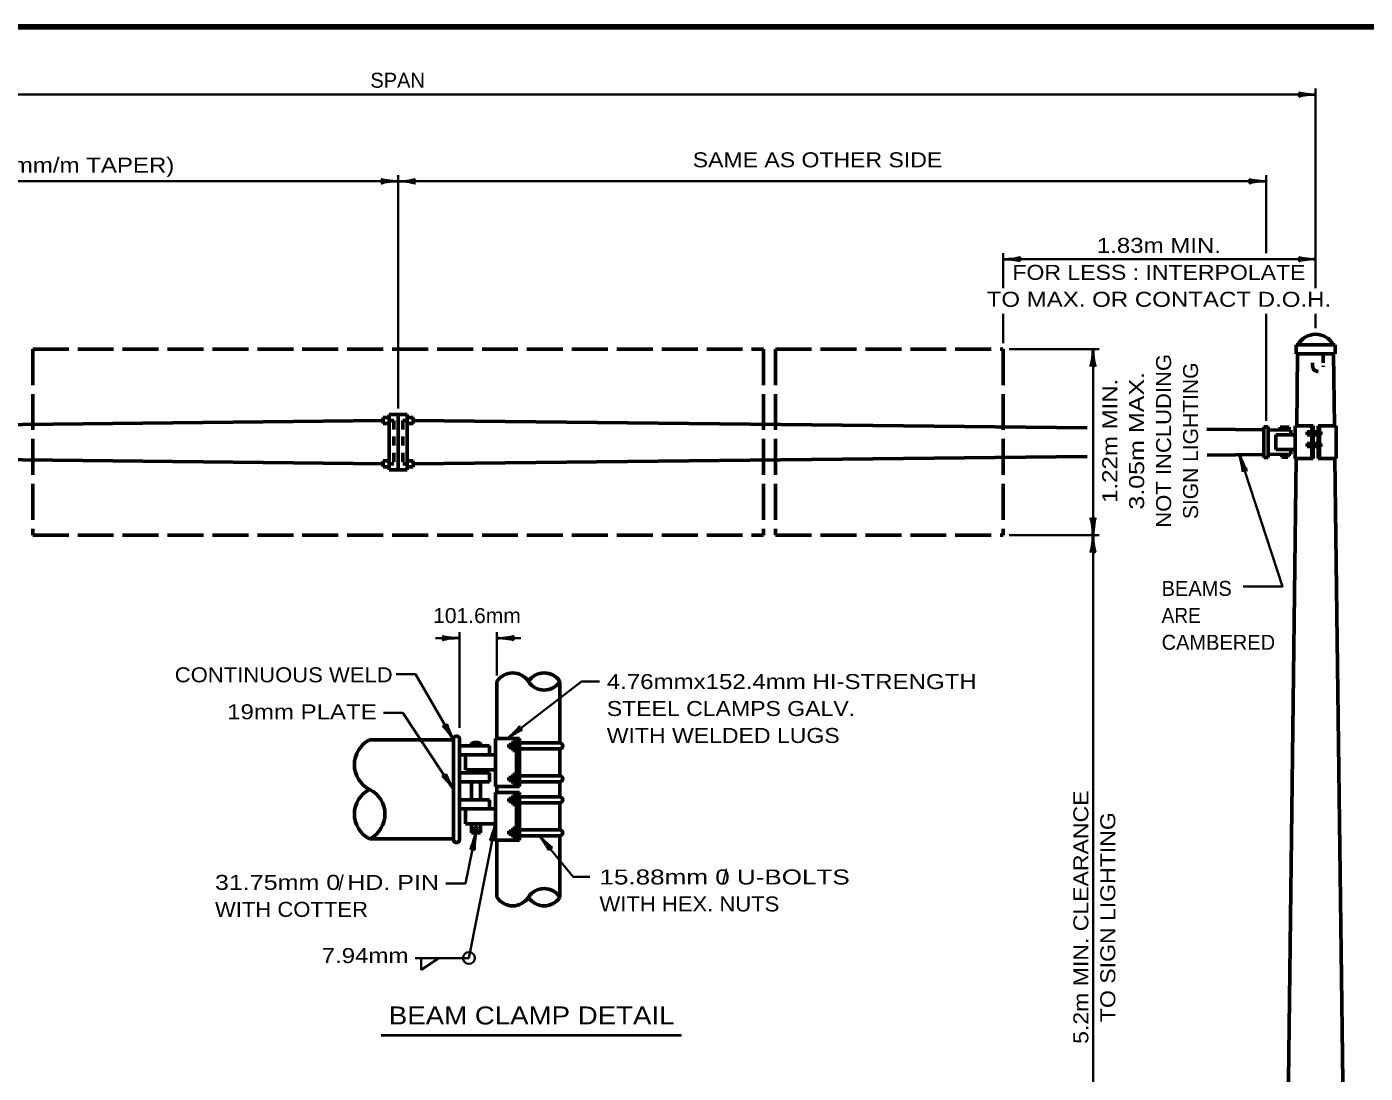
# Model space of a CAD drawing. Extents: x -46 to 809, y -15 to 529.
# Drawn here: x 209.6 to 477.7, y 313 to 522.6 of the extents above; entities that cross this region are included whole.
import ezdxf
from ezdxf.enums import TextEntityAlignment as Align

# ---------------------------------------------------------------- set-up
doc = ezdxf.new("R2010")
doc.units = 0
doc.header["$LTSCALE"] = 1.2
doc.linetypes.add('LONG_DASHED', pattern=[7.5, 6, -1.5])
doc.linetypes.add('SHORT_DASHED', pattern=[2.7, 1.5, -1.2])
doc.layers.add('1', color=7, linetype='Continuous', lineweight=35)

msp = doc.modelspace()

# ---------------------------------------------------------------- linework, layer by layer
at = {"layer": '1'}
for p, q in [((467.782, 470.197), (467.782, 510.163)), ((100.214, 508.963), (467.782, 508.963)), ((109.698, 491.614), (283.998, 491.614)), ((283.998, 446.114), (283.998, 492.814)), ((283.998, 491.614), (457.848, 491.614)), ((457.848, 477.203), (457.848, 492.814)), ((405.198, 470.197), (405.198, 477.203)), ((405.198, 476.003), (467.782, 476.003)), ((405.198, 459.203), (405.198, 465.037)), ((457.848, 443.614), (457.848, 465.037)), ((467.782, 462.163), (467.782, 465.037)), ((406.398, 458.003), (424.398, 458.003)), ((406.398, 420.725), (424.398, 420.725)), ((291.486, 400.126), (296.286, 400.126)), ((296.286, 382.126), (296.286, 401.326)), ((303.786, 392.626), (303.786, 401.326)), ((303.786, 400.126), (308.586, 400.126)), ((303.486, 362.925), (298.175, 336.055)), ((298.175, 336.055), (287.375, 336.055)), ((288.575, 336.055), (288.575, 333.655)), ((292.175, 336.055), (288.575, 333.655))]:
    msp.add_line(p, q, dxfattribs=at)
at = {"layer": '1', "lineweight": 53}
for p, q in [((471.682, 458.863), (463.882, 458.863)), ((463.882, 458.863), (463.882, 457.063)), ((471.682, 458.863), (471.682, 457.063)), ((471.682, 457.063), (463.882, 457.063)), ((464.182, 457.063), (463.998, 442.664)), ((471.382, 457.063), (471.566, 442.664)), ((110.598, 441.824), (280.998, 443.714)), ((280.998, 444.314), (280.998, 443.114)), ((280.998, 444.314), (282.198, 444.314)), ((280.998, 443.114), (282.198, 443.114)), ((282.198, 444.914), (282.198, 433.814)), ((282.198, 444.914), (283.998, 444.914)), ((283.998, 444.914), (283.998, 433.814)), ((285.798, 444.914), (283.998, 444.914)), ((285.798, 444.914), (285.798, 433.814)), ((286.998, 444.314), (285.798, 444.314)), ((286.998, 443.114), (285.798, 443.114)), ((286.998, 444.314), (286.998, 443.114)), ((421.998, 442.217), (286.998, 443.714)), ((457.398, 442.414), (457.398, 436.314)), ((458.298, 442.414), (457.398, 442.414)), ((458.298, 442.414), (458.298, 436.314)), ((463.698, 442.664), (467.298, 442.664)), ((463.698, 442.664), (463.698, 436.064)), ((466.998, 442.664), (466.998, 436.064)), ((467.298, 442.664), (467.298, 436.064)), ((471.866, 442.664), (468.266, 442.664)), ((468.266, 442.664), (468.266, 436.064)), ((468.566, 442.664), (468.566, 436.064)), ((471.866, 442.664), (471.866, 436.064)), ((457.398, 441.824), (446.011, 441.95)), ((462.798, 441.764), (458.298, 441.814)), ((459.798, 440.864), (459.798, 437.864)), ((459.798, 440.864), (463.698, 440.864)), ((460.698, 441.768), (460.698, 442.368)), ((462.498, 442.368), (460.698, 442.368)), ((462.498, 441.768), (462.498, 442.368)), ((462.798, 441.764), (462.798, 440.864)), ((466.698, 441.464), (466.098, 441.464)), ((466.098, 441.464), (466.098, 440.864)), ((466.698, 440.864), (466.098, 440.864)), ((466.998, 441.764), (466.698, 441.764)), ((466.698, 441.764), (466.698, 440.564)), ((466.998, 440.564), (466.698, 440.564)), ((468.266, 441.464), (467.298, 441.464)), ((468.266, 440.864), (467.298, 440.864)), ((459.798, 437.864), (463.698, 437.864)), ((462.798, 437.864), (462.798, 436.964)), ((466.698, 439.064), (466.098, 439.064)), ((466.098, 439.064), (466.098, 438.464)), ((466.698, 438.464), (466.098, 438.464)), ((466.998, 439.364), (466.698, 439.364)), ((466.698, 439.364), (466.698, 438.164)), ((466.998, 438.164), (466.698, 438.164)), ((468.266, 439.064), (467.298, 439.064)), ((468.266, 438.464), (467.298, 438.464)), ((110.598, 436.904), (280.998, 435.014)), ((280.998, 435.614), (280.998, 434.414)), ((280.998, 435.614), (282.198, 435.614)), ((280.998, 434.414), (282.198, 434.414)), ((286.998, 435.614), (285.798, 435.614)), ((286.998, 434.414), (285.798, 434.414)), ((421.998, 436.512), (286.998, 435.014)), ((286.998, 435.614), (286.998, 434.414)), ((457.398, 436.904), (446.068, 436.779)), ((458.298, 436.314), (457.398, 436.314)), ((462.798, 436.964), (458.298, 436.914)), ((460.998, 436.344), (460.998, 436.944)), ((462.198, 436.358), (460.998, 436.344)), ((463.914, 436.064), (461.782, 269.263)), ((462.198, 436.358), (462.198, 436.958)), ((463.698, 436.064), (467.298, 436.064)), ((471.866, 436.064), (468.266, 436.064)), ((471.651, 436.064), (473.782, 269.263)), ((282.198, 433.814), (283.998, 433.814)), ((285.798, 433.814), (283.998, 433.814)), ((303.786, 391.425), (303.786, 380.026)), ((316.386, 391.425), (316.386, 379.126)), ((295.086, 379.726), (278.286, 379.726)), ((295.086, 379.726), (295.086, 359.925)), ((296.286, 379.726), (296.286, 359.925)), ((296.286, 378.526), (302.286, 378.526)), ((302.286, 376.726), (302.286, 378.526)), ((308.286, 380.026), (303.486, 380.026)), ((303.486, 380.026), (303.486, 370.425)), ((306.936, 378.826), (306.186, 378.826)), ((306.186, 378.826), (306.186, 378.226)), ((306.936, 378.226), (306.186, 378.226)), ((307.686, 379.425), (306.936, 379.425)), ((306.936, 379.425), (306.936, 377.626)), ((307.686, 380.026), (307.686, 370.425)), ((308.286, 380.026), (308.286, 370.425)), ((308.286, 379.126), (316.386, 379.126)), ((296.286, 376.726), (303.486, 376.726)), ((297.486, 376.726), (297.486, 373.726)), ((307.686, 377.626), (306.936, 377.626)), ((308.286, 377.925), (316.386, 377.925)), ((316.386, 377.925), (316.386, 372.526)), ((296.286, 373.126), (302.286, 373.126)), ((297.486, 373.726), (303.486, 373.726)), ((298.686, 373.726), (298.686, 373.126)), ((300.486, 373.726), (300.486, 373.126)), ((302.286, 373.126), (302.286, 371.326)), ((307.686, 372.826), (306.936, 372.826)), ((306.936, 372.826), (306.936, 371.026)), ((296.286, 371.326), (302.286, 371.326)), ((298.686, 371.326), (298.686, 367.726)), ((300.486, 371.326), (300.486, 367.726)), ((308.286, 370.425), (303.486, 370.425)), ((303.786, 370.425), (303.786, 369.226)), ((306.936, 372.226), (306.186, 372.226)), ((306.186, 372.226), (306.186, 371.626)), ((306.936, 371.626), (306.186, 371.626)), ((307.686, 371.026), (306.936, 371.026)), ((308.286, 372.526), (316.386, 372.526)), ((308.286, 371.326), (316.386, 371.326)), ((316.386, 371.326), (316.386, 368.326)), ((296.286, 367.726), (302.286, 367.726)), ((302.286, 365.925), (302.286, 367.726)), ((308.286, 369.226), (303.486, 369.226)), ((303.486, 369.226), (303.486, 359.626)), ((306.936, 368.026), (306.186, 368.026)), ((306.186, 368.026), (306.186, 367.425)), ((306.936, 367.425), (306.186, 367.425)), ((307.686, 368.626), (306.936, 368.626)), ((306.936, 368.626), (306.936, 366.826)), ((307.686, 369.226), (307.686, 359.626)), ((308.286, 369.226), (308.286, 359.626)), ((308.286, 368.326), (316.386, 368.326)), ((296.286, 365.925), (303.486, 365.925)), ((297.486, 365.925), (297.486, 362.925)), ((307.686, 366.826), (306.936, 366.826)), ((308.286, 367.126), (316.386, 367.126)), ((316.386, 367.126), (316.386, 361.726)), ((297.486, 362.925), (303.486, 362.925)), ((298.686, 362.925), (298.686, 361.126)), ((300.486, 362.925), (300.486, 361.126)), ((307.686, 362.026), (306.936, 362.026)), ((306.936, 362.026), (306.936, 360.226)), ((295.086, 359.925), (278.286, 359.925)), ((298.686, 361.126), (300.486, 361.126)), ((308.286, 359.626), (303.486, 359.626)), ((303.786, 359.626), (303.786, 348.226)), ((306.936, 361.425), (306.186, 361.425)), ((306.186, 361.425), (306.186, 360.826)), ((306.936, 360.826), (306.186, 360.826)), ((307.686, 360.226), (306.936, 360.226)), ((308.286, 361.726), (316.386, 361.726)), ((308.286, 360.526), (316.386, 360.526)), ((316.386, 360.526), (316.386, 348.226))]:
    msp.add_line(p, q, dxfattribs=at)
at = {"layer": '1', "linetype": 'LONG_DASHED', "lineweight": 53}
for p, q in [((210.798, 458.003), (210.798, 420.725)), ((210.798, 458.003), (357.198, 458.003)), ((357.198, 458.003), (357.198, 420.725)), ((359.598, 458.003), (359.598, 420.725)), ((359.598, 458.003), (405.198, 458.003)), ((405.198, 458.003), (405.198, 420.725)), ((210.798, 420.725), (357.198, 420.725)), ((359.598, 420.725), (405.198, 420.725))]:
    msp.add_line(p, q, dxfattribs=at)
at = {"layer": '1', "linetype": 'SHORT_DASHED', "lineweight": 53}
for p, q in [((469.282, 457.063), (469.282, 454.663)), ((467.182, 455.263), (467.182, 454.663)), ((282.198, 443.714), (283.098, 443.714)), ((283.098, 443.714), (283.098, 435.014)), ((284.898, 443.714), (284.898, 435.014)), ((285.798, 443.714), (284.898, 443.714)), ((282.198, 435.014), (283.098, 435.014)), ((285.798, 435.014), (284.898, 435.014))]:
    msp.add_line(p, q, dxfattribs=at)
at = {"layer": '1', "lineweight": 40}
msp.add_line((280.598, 320.626), (340.722, 320.626), dxfattribs=at)
at = {"layer": '1', "lineweight": 158}
msp.add_lwpolyline([(802.618, 522.556), (10.918, 522.456), (11.018, -3.544)], dxfattribs=at)
at = {"layer": '1'}
for points in [[(423.198, 254.722), (423.198, 420.725), (423.198, 458.003)], [(452.547, 436.851), (461.153, 410.487), (453.261, 410.487)], [(295.086, 379.726), (287.463, 392.92), (283.586, 392.92)], [(305.886, 380.026), (320.718, 391.428), (324.297, 391.428)], [(295.086, 369.826), (284.928, 385.163), (281.051, 385.163)], [(299.586, 361.126), (297.455, 351.002), (293.578, 351.002)], [(312.336, 360.526), (319.078, 352.345), (322.359, 352.345)]]:
    msp.add_lwpolyline(points, dxfattribs=at)
at = {"layer": '1', "lineweight": 53}
msp.add_circle((299.559, 361.893), 0.3, dxfattribs=at)
at = {"layer": '1'}
msp.add_circle((298.175, 336.055), 1.2, dxfattribs=at)
at = {"layer": '1', "lineweight": 53}
for centre, radius, start, end in [((467.782, 456.866), 4.097, 29.1749, 150.8251), ((468.524, 441.164), 0.303, 278.06402, 81.93598), ((468.524, 438.764), 0.303, 278.06402, 81.93598), ((306.936, 389.398), 3.746, 32.77246, 147.22754), ((313.236, 389.398), 3.746, 32.77246, 147.22754), ((313.236, 393.453), 3.746, 212.77246, 327.22754), ((280.747, 374.776), 5.528, 116.42698, 243.57302), ((295.686, 379.873), 0.618, 346.19132, 193.80868), ((299.586, 377.891), 1.357, 27.87518, 152.12482), ((316.353, 378.526), 0.601, 273.15116, 86.84884), ((316.353, 371.926), 0.601, 273.15116, 86.84884), ((280.747, 364.876), 5.528, 116.42698, 243.57302), ((275.826, 364.876), 5.528, 296.42698, 63.57302), ((316.353, 367.726), 0.601, 273.15116, 86.84884), ((295.686, 359.778), 0.618, 166.19132, 13.80868), ((316.353, 361.126), 0.601, 273.15116, 86.84884), ((313.236, 346.198), 3.746, 32.77246, 147.22754), ((306.936, 350.253), 3.746, 212.77246, 327.22754), ((313.236, 350.253), 3.746, 212.77246, 327.22754)]:
    msp.add_arc(centre, radius, start, end, dxfattribs=at)
at = {"layer": '1', "linetype": 'SHORT_DASHED', "lineweight": 53}
msp.add_arc((468.232, 454.596), 1.052, 176.35082, 3.64918, dxfattribs=at)
at = {"layer": '1', "lineweight": 40}
for centre, major_axis, ratio, start_param, end_param in [((466.438, 509.217), (2.108, -0.211), 0.07063, 3.1407148, 5.41811), ((466.473, 508.631), (2.143, 0.187), 0.122415, 0.8963533, 3.1415927), ((282.689, 491.283), (2.143, 0.187), 0.122415, 0.8963533, 3.1415927), ((282.654, 491.868), (2.108, -0.211), 0.07063, 3.1407148, 5.41811), ((285.343, 491.36), (-2.108, 0.211), 0.07063, 3.1407148, 5.41811), ((285.343, 491.36), (-2.108, 0.211), 0.07063, 3.1407148, 5.41811), ((285.308, 491.946), (-2.143, -0.187), 0.122415, 0.8963533, 3.1415927), ((285.308, 491.946), (-2.143, -0.187), 0.122415, 0.8963533, 3.1415927), ((456.539, 491.283), (2.143, 0.187), 0.122415, 0.8963533, 3.1415927), ((456.504, 491.868), (2.108, -0.211), 0.07063, 3.1407148, 5.41811), ((406.543, 475.749), (-2.108, 0.211), 0.07063, 3.1407148, 5.41811), ((406.543, 475.749), (-2.108, 0.211), 0.07063, 3.1407148, 5.41811), ((406.508, 476.335), (-2.143, -0.187), 0.122415, 0.8963533, 3.1415927), ((406.508, 476.335), (-2.143, -0.187), 0.122415, 0.8963533, 3.1415927), ((466.473, 475.672), (2.143, 0.187), 0.122415, 0.8963533, 3.1415927), ((466.438, 476.257), (2.108, -0.211), 0.07063, 3.1407148, 5.41811), ((422.944, 456.658), (0.211, 2.108), 0.07063, 3.1407148, 5.41811), ((422.944, 456.658), (0.211, 2.108), 0.07063, 3.1407148, 5.41811), ((423.53, 456.694), (-0.187, 2.143), 0.122415, 0.8963533, 3.1415927), ((423.53, 456.694), (-0.187, 2.143), 0.122415, 0.8963533, 3.1415927), ((452.723, 435.493), (0.454, -2.069), 0.07063, 6.2823074, 8.5597026), ((453.269, 435.709), (-0.843, 1.979), 0.122415, 0.8963533, 3.1415927), ((422.867, 422.035), (0.187, -2.143), 0.122415, 0.8963533, 3.1415927), ((422.867, 422.035), (0.187, -2.143), 0.122415, 0.8963533, 3.1415927), ((423.452, 422.07), (-0.211, -2.108), 0.07063, 3.1407148, 5.41811), ((423.452, 422.07), (-0.211, -2.108), 0.07063, 3.1407148, 5.41811), ((422.944, 419.381), (0.211, 2.108), 0.07063, 3.1407148, 5.41811), ((423.53, 419.416), (-0.187, 2.143), 0.122415, 0.8963533, 3.1415927), ((294.977, 399.794), (2.143, 0.187), 0.122415, 0.8963533, 3.1415927), ((294.942, 400.379), (2.108, -0.211), 0.07063, 3.1407148, 5.41811), ((305.131, 399.872), (-2.108, 0.211), 0.07063, 3.1407148, 5.41811), ((305.131, 399.872), (-2.108, 0.211), 0.07063, 3.1407148, 5.41811), ((305.096, 400.457), (-2.143, -0.187), 0.122415, 0.8963533, 3.1415927), ((305.096, 400.457), (-2.143, -0.187), 0.122415, 0.8963533, 3.1415927), ((294.144, 380.693), (1.234, -1.762), 0.122415, 0.8963533, 3.1415927), ((294.144, 380.693), (1.234, -1.762), 0.122415, 0.8963533, 3.1415927), ((294.634, 381.017), (-0.872, 1.93), 0.07063, 6.2823074, 8.5597026), ((294.634, 381.017), (-0.872, 1.93), 0.07063, 6.2823074, 8.5597026), ((306.722, 381.086), (-1.585, -1.455), 0.122415, 0.8963533, 3.1415927), ((306.722, 381.086), (-1.585, -1.455), 0.122415, 0.8963533, 3.1415927), ((307.107, 380.644), (1.799, 1.118), 0.07063, 6.2823074, 8.5597026), ((307.107, 380.644), (1.799, 1.118), 0.07063, 6.2823074, 8.5597026), ((294.556, 371.087), (-0.988, 1.874), 0.07063, 6.2823074, 8.5597026), ((294.556, 371.087), (-0.988, 1.874), 0.07063, 6.2823074, 8.5597026), ((294.087, 370.734), (1.339, -1.683), 0.122415, 0.8963533, 3.1415927), ((294.087, 370.734), (1.339, -1.683), 0.122415, 0.8963533, 3.1415927), ((302.977, 361.656), (-0.615, -2.027), 0.07063, 6.2823074, 8.5597026), ((303.558, 361.577), (0.232, 2.139), 0.122415, 0.8963533, 3.1415927), ((299.061, 359.862), (-0.641, -2.019), 0.07063, 6.2823074, 8.5597026), ((299.061, 359.862), (-0.641, -2.019), 0.07063, 6.2823074, 8.5597026), ((299.641, 359.776), (0.258, 2.135), 0.122415, 0.8963533, 3.1415927), ((299.641, 359.776), (0.258, 2.135), 0.122415, 0.8963533, 3.1415927), ((312.996, 359.326), (1.178, -1.761), 0.07063, 6.2823074, 8.5597026), ((312.996, 359.326), (1.178, -1.761), 0.07063, 6.2823074, 8.5597026), ((313.425, 359.726), (-1.507, 1.535), 0.122415, 0.8963533, 3.1415927), ((313.425, 359.726), (-1.507, 1.535), 0.122415, 0.8963533, 3.1415927)]:
    msp.add_ellipse(centre, major_axis=major_axis, ratio=ratio, start_param=start_param, end_param=end_param, dxfattribs=at)

# ---------------------------------------------------------------- texts
at = {"layer": '1'}
for s, p in [('SPAN', (283.888, 510.344)), ('/', (349.366, 350.768)), ('/', (272.556, 349.679))]:
    msp.add_text(s, height=3, dxfattribs=at).set_placement(p, align=Align.CENTER)
for s, height, width, p in [('ROUND MONOTUBE (12mm/m TAPER)', 3, 1.2, (195.428, 493.356)), ('SAME AS OTHER SIDE', 3, 1.15, (367.996, 494.411)), ('1.83m MIN.', 3, 1.2, (436.387, 477.275)), ('FOR LESS : INTERPOLATE', 3, 1.15, (436.387, 471.875)), ('TO MAX. OR CONTACT D.O.H.', 3, 1.2, (436.387, 466.475)), ('101.6mm', 3, 1.05, (299.784, 403.141)), ('CONTINUOUS WELD', 3, 1.1, (261.068, 391.271)), ('19mm PLATE', 3, 1.2, (264.722, 383.869)), ('7.94mm', 3, 1.2, (277.366, 335.043)), ('BEAM CLAMP DETAIL', 3.6, 1.15, (310.736, 322.748))]:
    msp.add_text(s, height=height, dxfattribs=dict(at, width=width)).set_placement(p, align=Align.CENTER)
for s, width, p in [('NOT INCLUDING', 1.1, (438.826, 439.632)), ('SIGN LIGHTING', 1.05, (444.226, 439.632)), ('1.22m MIN.', 1.2, (428.026, 439.632)), ('3.05m MAX.', 1.25, (433.425, 439.632)), ('5.2m MIN. CLEARANCE', 1.15, (422.25, 344.234)), ('TO SIGN LIGHTING', 1.15, (427.65, 344.234))]:
    msp.add_text(s, height=3, rotation=90, dxfattribs=dict(at, width=width)).set_placement(p, align=Align.CENTER)
for s, p in [('BEAMS', (436.931, 408.576)), ('CAMBERED', (436.931, 397.776))]:
    msp.add_text(s, height=3, dxfattribs=at).set_placement(p)
for s, width, p in [('ARE', 0.95, (436.931, 403.176)), ('4.76mmx152.4mm HI-STRENGTH', 1.2, (325.788, 389.92)), ('STEEL CLAMPS GALV.', 1.15, (325.788, 384.52)), ('WITH WELDED LUGS', 1.15, (325.788, 379.12)), ('31.75mm 0 HD. PIN', 1.25, (247.301, 349.7)), ('15.88mm 0 U-BOLTS', 1.3, (324.319, 350.78)), ('WITH COTTER', 1.1, (247.301, 344.3)), ('WITH HEX. NUTS', 1.1, (324.319, 345.38))]:
    msp.add_text(s, height=3, dxfattribs=dict(at, width=width)).set_placement(p)

doc.saveas('drawing.dxf')
